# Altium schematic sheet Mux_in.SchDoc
size A4
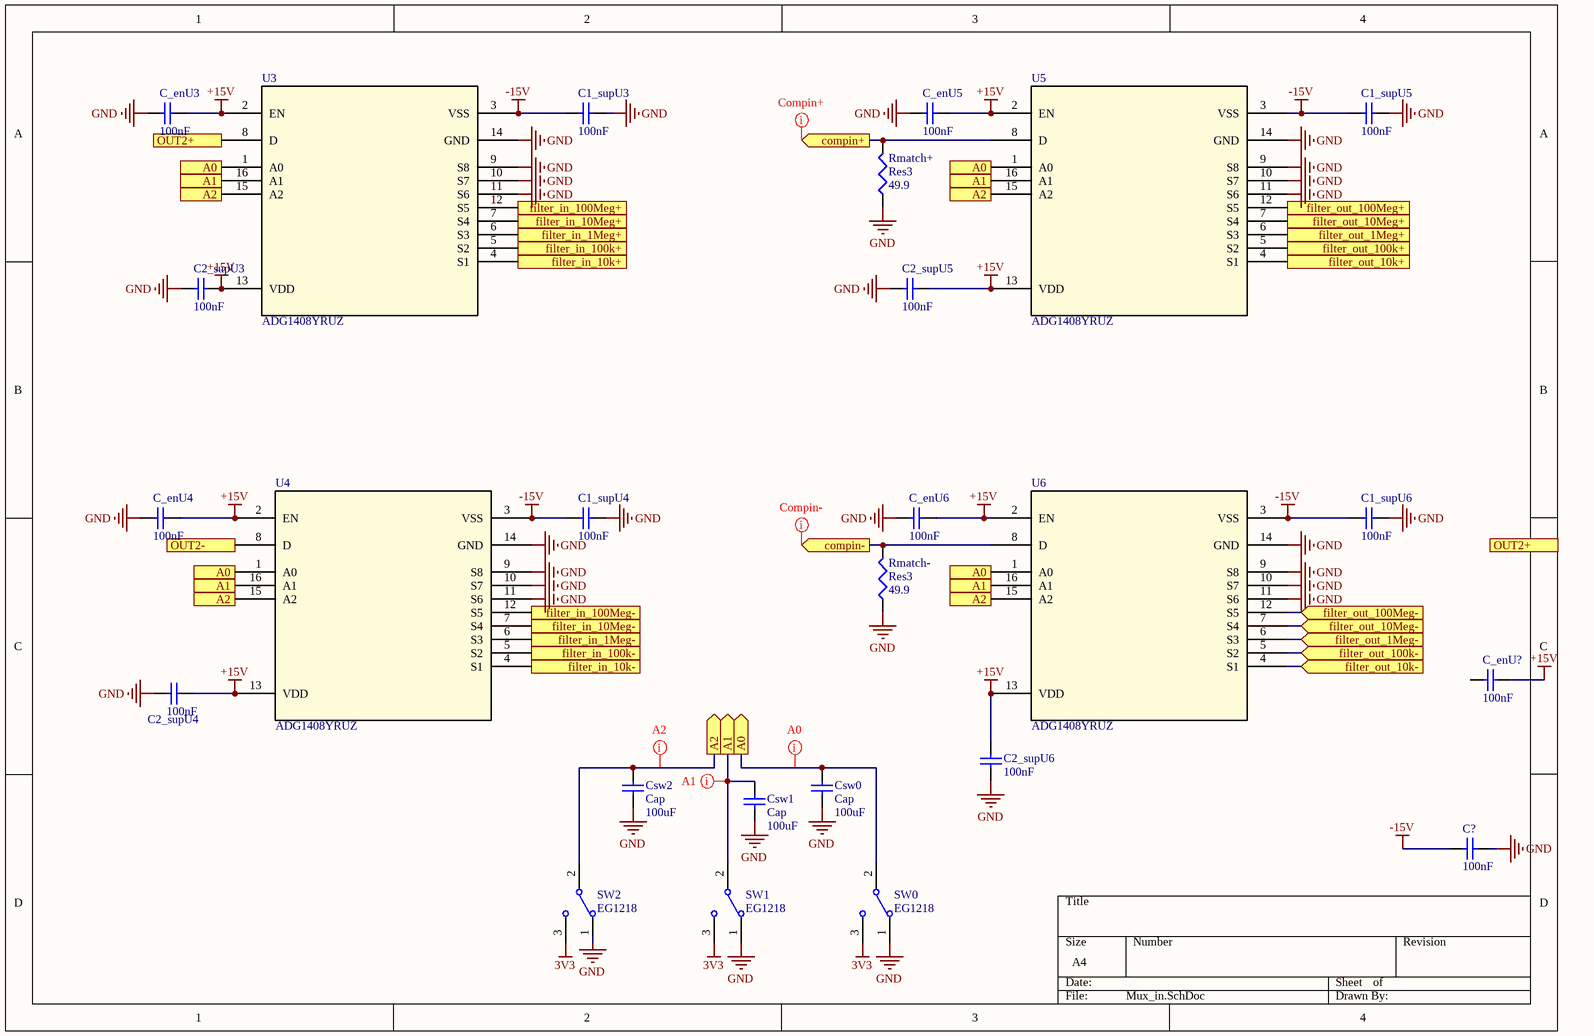
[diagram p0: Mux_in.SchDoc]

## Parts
C1_supU3  value 100nF  [J1-0603]  (hidden comment: Cap Semi)
C1_supU4  value 100nF  [J1-0603]  (hidden comment: Cap Semi)
C1_supU5  value 100nF  [J1-0603]  (hidden comment: Cap Semi)
C1_supU6  value 100nF  [J1-0603]  (hidden comment: Cap Semi)
C2_supU3  value 100nF  [J1-0603]  (hidden comment: Cap Semi)
C2_supU4  value 100nF  [J1-0603]  (hidden comment: Cap Semi)
C2_supU5  value 100nF  [J1-0603]  (hidden comment: Cap Semi)
C2_supU6  value 100nF  [J1-0603]  (hidden comment: Cap Semi)
C?  value 100nF  [J1-0603]  (hidden comment: Cap Semi)
C_enU3  value 100nF  [J1-0603]  (hidden comment: Cap Semi)
C_enU4  value 100nF  [J1-0603]  (hidden comment: Cap Semi)
C_enU5  value 100nF  [J1-0603]  (hidden comment: Cap Semi)
C_enU6  value 100nF  [J1-0603]  (hidden comment: Cap Semi)
C_enU?  value 100nF  [J1-0603]  (hidden comment: Cap Semi)
Csw0  Cap  value 100uF  [J1-0603]
Csw1  Cap  value 100uF  [J1-0603]
Csw2  Cap  value 100uF  [J1-0603]
Rmatch+  Res3  value 49.9  [6-0805_M]
Rmatch-  Res3  value 49.9  [6-0805_M]
SW0  EG1218  [ESWI-EG1218_V]
SW1  EG1218  [ESWI-EG1218_V]
SW2  EG1218  [ESWI-EG1218_V]
U3  ADG1408YRUZ  [RU_16_ADI]
U4  ADG1408YRUZ  [RU_16_ADI]
U5  ADG1408YRUZ  [RU_16_ADI]
U6  ADG1408YRUZ  [RU_16_ADI]

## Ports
A0, A0 (out), A1, A1 (out), A2, A2 (out), compin+ (out), compin- (out), filter_in_1Meg+ (out), filter_in_1Meg- (out), filter_in_10k+ (out), filter_in_10k- (out), filter_in_10Meg+ (out), filter_in_10Meg- (out), filter_in_100k+ (out), filter_in_100k- (out), filter_in_100Meg+ (out), filter_in_100Meg- (out), filter_out_1Meg+ (in), filter_out_1Meg- (in), filter_out_10k+ (in), filter_out_10k- (in), filter_out_10Meg+ (in), filter_out_10Meg- (in), filter_out_100k+ (in), filter_out_100k- (in), filter_out_100Meg+ (in), filter_out_100Meg- (in), OUT2+ (in), OUT2- (in)

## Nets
3V3: SW0.3 SW1.3 SW2.3
+15V: C2_supU3.2 C2_supU4.2 C2_supU5.2 C2_supU6.2 C_enU3.2 C_enU4.2 C_enU5.2 C_enU6.2 C_enU?.2 U3.2(EN) U3.13(VDD) U4.2(EN) U4.13(VDD) U5.2(EN) U5.13(VDD) U6.2(EN) U6.13(VDD)
-15V: C1_supU3.2 C1_supU4.2 C1_supU5.2 C1_supU6.2 C?.2 U3.3(VSS) U4.3(VSS) U5.3(VSS) U6.3(VSS)
GND: C1_supU3.1 C1_supU4.1 C1_supU5.1 C1_supU6.1 C2_supU3.1 C2_supU4.1 C2_supU5.1 C2_supU6.1 C?.1 C_enU3.1 C_enU4.1 C_enU5.1 C_enU6.1 Csw0.1 Csw1.1 Csw2.1 Rmatch+.1 Rmatch-.1 SW0.1 SW1.1 SW2.1 U3.9(S8) U3.10(S7) U3.11(S6) U3.14(GND) U4.9(S8) U4.10(S7) U4.11(S6) U4.14(GND) U5.9(S8) U5.10(S7) U5.11(S6) U5.14(GND) U6.9(S8) U6.10(S7) U6.11(S6) U6.14(GND)
A0: Csw0.2 SW0.2(COM) U3.1(A0) U4.1(A0) U5.1(A0) U6.1(A0) ; port A0
A1: Csw1.2 SW1.2(COM) U3.16(A1) U4.16(A1) U5.16(A1) U6.16(A1) ; port A1
A2: Csw2.2 SW2.2(COM) U3.15(A2) U4.15(A2) U5.15(A2) U6.15(A2) ; port A2
compin+: Rmatch+.2 U5.8(D) ; port compin+
compin-: Rmatch-.2 U6.8(D) ; port compin-
filter_in_1Meg+: U3.6(S3) ; port filter_in_1Meg+
filter_in_1Meg-: U4.6(S3) ; port filter_in_1Meg-
filter_in_10k+: U3.4(S1) ; port filter_in_10k+
filter_in_10k-: U4.4(S1) ; port filter_in_10k-
filter_in_10Meg+: U3.7(S4) ; port filter_in_10Meg+
filter_in_10Meg-: U4.7(S4) ; port filter_in_10Meg-
filter_in_100k+: U3.5(S2) ; port filter_in_100k+
filter_in_100k-: U4.5(S2) ; port filter_in_100k-
filter_in_100Meg+: U3.12(S5) ; port filter_in_100Meg+
filter_in_100Meg-: U4.12(S5) ; port filter_in_100Meg-
filter_out_1Meg+: U5.6(S3) ; port filter_out_1Meg+
filter_out_1Meg-: U6.6(S3) ; port filter_out_1Meg-
filter_out_10k+: U5.4(S1) ; port filter_out_10k+
filter_out_10k-: U6.4(S1) ; port filter_out_10k-
filter_out_10Meg+: U5.7(S4) ; port filter_out_10Meg+
filter_out_10Meg-: U6.7(S4) ; port filter_out_10Meg-
filter_out_100k+: U5.5(S2) ; port filter_out_100k+
filter_out_100k-: U6.5(S2) ; port filter_out_100k-
filter_out_100Meg+: U5.12(S5) ; port filter_out_100Meg+
filter_out_100Meg-: U6.12(S5) ; port filter_out_100Meg-
OUT2+: U3.8(D) ; port OUT2+
OUT2-: U4.8(D) ; port OUT2-

Not connected (* = marked no-connect by the designer): C_enU? 1

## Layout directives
mark named A2: A2
mark named A1: A1
mark named A0: A0
mark named Compin+: compin+
mark named Compin-: compin-

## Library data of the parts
C1_supU3-C1_supU6 C2_supU3-C2_supU6 C? C_enU3-C_enU6 C_enU? = Cap Semi: Capacitor (Semiconductor SIM Model)
Csw0-Csw2 = Cap: Capacitor
Rmatch+ Rmatch- = Res3: Resistor
SW0-SW2 = CMP-011-00006-1: Slide Switch, SPDT, 500 V, -20 to 70 degC, 3-Pin THD, RoHS, Bulk; Manufacturer: E-Switch; Operating Force: 250gf; Contact Current Rating: 200mA; Current Rating: 2dA; Voltage Rating (DC): 30V
U3-U6 = ADG1408YRUZ: No Description Available; Vendor: Analog Devices Inc; Built_By: EMA_UL_Team; SourceLibrary: Analog_2015-12-15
